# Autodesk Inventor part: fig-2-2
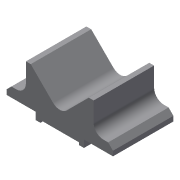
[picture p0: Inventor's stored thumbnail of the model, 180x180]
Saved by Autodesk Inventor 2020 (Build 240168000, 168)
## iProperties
Part Number: fig-2-2
Document SubType Name: Modeling
Created: 2002-11
Designer: deepak
Density: 1 g/cm^3
Material: Generic
Appearance: Default
Control State: 0
Master: False
Checked Out: False
Shininess: 64.0
Length Units: 11269
Angle Units: 11279
Time Units: 11290
Mass Units: 11283
Length Display Precision: 3
Angle Display Precision: 2
Compacted: True
Density: 0.0
Volumn: 0.0
Area: 0.0
PropertySet Name: Model Information
Author: CADCIM
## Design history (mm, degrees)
sketch "Sketch1"
  geometry: L1 (0, 0)-(-3, 3); L2 (-3, 3)-(-3.5, 3); L3 (-3.5, 3)-(-3.5, 0); L4 (-3.5, 0)-(-5.5, 0); L5 (-5.5, 0)-(-5.5, -1); L6 (-5.5, -1)-(-2.5, -1); L7 (-2.5, -1)-(-2.5, -1.75); L8 (-2.5, -1.75)-(-2, -1.75); L9 (-2, -1.75)-(-2, -1.5); L10 (-2, -1.5)-(2, -1.5); L11 (2, -1.5)-(2, -1.75); L12 (2, -1.75)-(2.5, -1.75); L13 (2.5, -1.75)-(2.5, -1); L14 (2.5, -1)-(5.5, -1); L15 (5.5, -1)-(5.5, 0); L16 (5.5, 0)-(3.5, 0); L17 (3.5, 0)-(3.5, 3); L18 (3.5, 3)-(3, 3); L19 (3, 3)-(0, 0)
  constraints: 38 end point, 17 perpendicular, 1 horizontal
extrude "Extrusion1" new body sketch "Sketch1" distance "d0" = 6.25; taper "d1" = 0 deg
fillet "Fillet1" dims "d2" = 1
chamfer "Chamfer1" distance "d3" = 0.5; stored, may be unused: second distance "d4" = 2, angle "d5" = 45 deg
body "Solid1"
